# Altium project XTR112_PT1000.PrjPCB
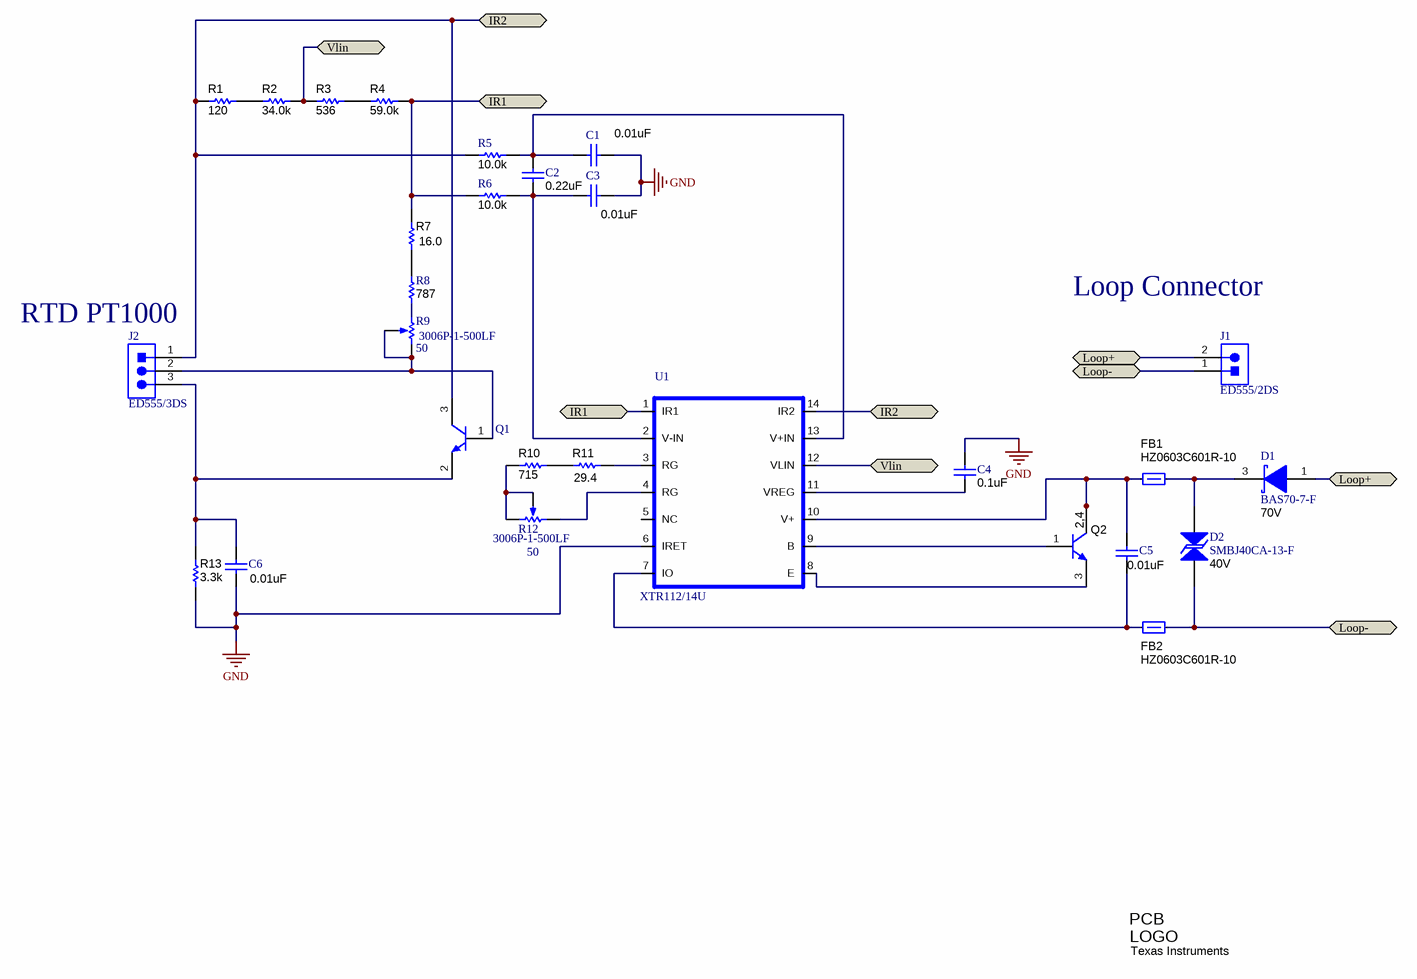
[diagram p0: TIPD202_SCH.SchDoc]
TechSupport: http://www.ti.com/support; SCH_Rev: A; PRJ_Title: Linearized 3-wire PT1000 RTD to 2-wire 4-20mA; PRJ_Customer: Public Release; PRJ_BasePN: TIPD202; PCB_SilkRev: REV A; PCB_CopperRev: 001; CopyrightYear: 2015
1 sheet, 29 parts. Net scope: flat (ports and power ports of the same name join across sheets).
Board file: XTR112_PT1000.PcbDoc

## Sheet TIPD202_SCH.SchDoc: TIPD202 Schematic
size 431 x 279 mm; Date: Not shown in title block; ApprovedBy: Not shown in title block; CheckedBy: Not shown in title block; Author: Not shown in title block; CompanyName: Not shown in title block; Engineer: Not shown in title block; Organization: Not shown in title block; Address1: Not shown in title block; Address2: Not shown in title block; Address3: Not shown in title block; Address4: Not shown in title block; DocumentNumber: 1; Revision: Use project parameter SCH_Rev; SheetNumber: 1; SheetTotal: 1; PageSetup: Record=PageOptions¦CenterHorizontal=True¦CenterVertical=True¦PrintScale=1.00¦XCorrection=1.00¦YCorrection=1.00¦PrintKind=0¦BorderSize=5000000¦LeftOffset=0¦BottomOffset=0¦Orientation=2¦PaperLength=1000¦PaperWidth=1000¦Scale=100¦PaperSource=15¦PrintQuality=600¦MediaType=1¦DitherType=10¦PaperKind=Letter¦PrintScaleMode=1

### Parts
C1  value 0.01uF  [0805_HV]  (hidden comment: C2012C0G1H103J)
C2  value 0.22uF  [0805_HV]  (hidden comment: GRM21BR71H224KA01L)
C3  value 0.01uF  [0805_HV]  (hidden comment: C2012C0G1H103J)
C4  value 0.1uF  [0805_HV]  (hidden comment: 08055C104KAT2A)
C5  value 0.01uF  [0805_HV]  (hidden comment: GRM216R71H103KA01D)
C6  value 0.01uF  [0805_HV]  (hidden comment: GRM216R71H103KA01D)
D1  BAS70-7-F  value 70V  [SOT-23]
D2  SMBJ40CA-13-F  value 40V  [SMB]
FB1  value HZ0603C601R-10  [0603]  (hidden comment: Used in BOM report)
FB2  value HZ0603C601R-10  [0603]  (hidden comment: Used in BOM report)
J1  ED555/2DS  [TERM_BLK_ED555-2DS]
J2  ED555/3DS  [TERM_BLK_ED555-3DS]
Logo1  Texas Instruments  [TI_Stacked_Overlay_Small]  (no BOM)
Q1  BC847CLT1G  [SOT-23]  (value not drawn)
Q2  FCX690BTA  [SOT-89-3]  (value not drawn)
R1  ValueDisplayed: 120  [0805_HV]  (hidden comment: RG2012P-121-B-T5)
R2  ValueDisplayed: 34.0k  [0805_HV]  (hidden comment: RT0805BRD0734KL)
R3  ValueDisplayed: 536  [0805_HV]  (hidden comment: RT0805BRD07536RL)
R4  ValueDisplayed: 59.0k  [0805_HV]  (hidden comment: RT0805BRD0759KL)
R5  value 10.0k  [0805_HV]  (hidden comment: CRCW080510K0FKEA)
R6  value 10.0k  [0805_HV]  (hidden comment: CRCW080510K0FKEA)
R7  value 16.0  [0805_HV]  (hidden comment: RT0805BRD0716RL)
R8  value 787  [0805_HV]  (hidden comment: RT0805BRD07787RL)
R9  3006P-1-500LF  value 50  [BOURNS_3006P]
R10  ValueDisplayed: 715  [0805_HV]  (hidden comment: RT0805BRD07715RL)
R11  value 29.4  [0805_HV]  (hidden comment: RT0805BRD0729R4L)
R12  3006P-1-500LF  value 50  [BOURNS_3006P]
R13  ValueDisplayed: 3.3k  [0805_HV]  (hidden comment: CRCW08053K30JNEA)
U1  XTR112/14U  [SO14]

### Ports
IR1, IR2, Loop+, Loop-, Vlin

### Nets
GND: C1.1 C3.1 C4.1 C6.2 R13.1 U1.6(IRET)
NetC1_2: C1.2 C2.1 R5.2 U1.13(V+IN)
NetC2_2: C2.2 C3.2 R6.2 U1.2(V-IN)
NetC4_2: C4.2 U1.11(VREG)
NetC5_1: C5.1 FB1.1 Q2.2(C) Q2.4(C) U1.10(V+)
NetC5_2: C5.2 FB2.1 U1.7(IO)
NetC6_1: C6.1 J2.3 Q1.2(E) R13.2
NetD1_1: D1.1(A) J1.2 ; port Loop+
NetD1_3: D1.3(K) D2.2 FB1.2
NetD2_1: D2.1 FB2.2 J1.1 ; port Loop-
NetJ2_1: J2.1 Q1.3(C) R1.1 R5.1 U1.14(IR2) ; port IR2
NetJ2_2: J2.2 Q1.1(B) R9.2(WIPER) R9.3(CW)
NetQ2_1: Q2.1(B) U1.9(B)
NetQ2_3: Q2.3(E) U1.8(E)
NetR1_2: R1.2 R2.1
NetR2_2: R2.2 R3.1 U1.12(VLIN) ; port Vlin
NetR3_2: R3.2 R4.1
NetR4_2: R4.2 R6.1 R7.2 U1.1(IR1) ; port IR1
NetR7_1: R7.1 R8.2
NetR8_1: R8.1 R9.1(CCW)
NetR10_1: R10.1 R12.2(WIPER) R12.3(CW)
NetR10_2: R10.2 R11.1
NetR11_2: R11.2 U1.3(RG)
NetR12_1: R12.1(CCW) U1.4(RG)

Not connected (* = marked no-connect by the designer): U1 5(NC)

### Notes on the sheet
- (near J2) RTD PT1000
- Loop Connector

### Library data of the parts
C1 C3 = C2012C0G1H103J: CAP, CERM, 0.01uF, 50V, +/-5%, C0G/NP0, 0805; Manufacturer: TDK; Polarized: N; CompType: Capacitor; ValueDisplayed: 0.01µF; U/M: EA; Cap_F: 0.00000001; Tolerance_%: 5; Value1: Unknown; VDC_V: 50; TaMin_C: -55; TaMax_C: 125; Cap_Case: 0805
C2 = GRM21BR71H224KA01L: CAP, CERM, 0.22uF, 50V, +/-10%, X7R, 0805; Manufacturer: MuRata; Polarized: N; CompType: Capacitor; ValueDisplayed: 0.22µF; U/M: EA; Cap_F: 0.00000022; Tolerance_%: 10; Value1: Unknown; VDC_V: 50; TaMin_C: -55; TaMax_C: 125; Cap_Case: 0805
C4 = 08055C104KAT2A: CAP, CERM, 0.1uF, 50V, +/-10%, X7R, 0805; Manufacturer: AVX; Polarized: N; CompType: Capacitor; ValueDisplayed: 0.1µF; U/M: EA; Cap_F: 0.0000001; Tolerance_%: 10; ESR_Ohm: 0.024; Value1: 0.024 ohm; VDC_V: 50; TaMin_C: -55; TaMax_C: 125; Cap_Case: 0805
C5 C6 = GRM216R71H103KA01D: CAP, CERM, 0.01uF, 50V, +/-10%, X7R, 0805; Manufacturer: MuRata; Polarized: N; CompType: Capacitor; ValueDisplayed: 0.01µF; U/M: EA; Cap_F: 0.00000001; Tolerance_%: 10; Value1: Unknown; VDC_V: 50; TaMin_C: -55; TaMax_C: 125; Cap_Case: 0805
D1 = BAS70-7-F: Diode, Schottky, 70V, 0.07A, SOT-23; Manufacturer: Diodes Inc.; U/M: EA; Vf_V: 0.41; Value2: 0.41V; Io_A: 0.07; Vr_V: 70; TJmax_C: 125
D2 = SMBJ40CA-13-F: Diode, TVS, Bi, 40V, 600W, SMB; Manufacturer: Diodes Inc.; U/M: EA; Power_W: 600; Vr_V: 40
FB1 FB2 = Ferrite_Bead: 300mA Ferrite Bead, 600 ohm @ 100MHz; U/M: EA
J1 = ED555/2DS: Terminal Block, 6A, 3.5mm Pitch, 2-Pos, TH; Manufacturer: On-Shore Technology; SymbolCreator: a0412235; CompType: Connector; U/M: EA
J2 = ED555/3DS: Terminal Block, 6A, 3.5mm Pitch, 3-Pos, TH; Manufacturer: On-Shore Technology; SymbolCreator: a0799628; CompType: Connector; U/M: EA
Logo1 = TI_Logo: Texas Instrument Corporate Signature; SymbolCreator: a0412235
Q1 = BC847CLT1G, ON Semiconductor: Transistor, NPN, 45V, 0.1A, SOT-23; CompType: BJT; PNP: 0; NPN: 1; Vceo_V: 45; Vcesat1_V: 0.7; Value: 0.7V; IcRated_A: 0.1; HfeMax: 800; TaMin_C: -55; TaMax_C: 150; U/M: EA
Q2 = FCX690BTA, Diodes Inc.: Transistor, NPN, 45V, 1A, SOT-89; Alternate Manufacturer: None; CompType: BJT; U/M: EA; PNP: 0; NPN: 1; Vceo_V: 45; Vcesat1_V: 0.08; Value: 0.08V
R1 = RG2012P-121-B-T5: RES, 120, 0.1%, 0.125 W, 0805; Manufacturer: Susumu Co Ltd; CompType: Resistor; Value: 120; Value_Code: 120R; Tolerance_%: 0.1; Power_W: 0.125; Value2: 0.125W; VDC_V: 100; TempCo: 25 ppm/C; EIA_Code: E192; U/M: EA
R2 = RT0805BRD0734KL: RES, 34.0 k, 0.1%, 0.125 W, 0805; Manufacturer: Yageo America; CompType: Resistor; Value: 34.0k; Res_ohm: 34000; Value_Code: 34k0; Tolerance_%: 0.1; Power_W: 0.125; Value2: 0.125W; VDC_V: 150; TempCo: 25 ppm/C; EIA_Code: E192; U/M: EA
R3 = RT0805BRD07536RL: RES, 536, 0.1%, 0.125 W, 0805; Manufacturer: Yageo America; CompType: Resistor; Value: 536; Value_Code: 536R; Tolerance_%: 0.1; Power_W: 0.125; Value2: 0.125W; VDC_V: 150; TempCo: 25 ppm/C; EIA_Code: E192; U/M: EA
R4 = RT0805BRD0759KL: RES, 59.0 k, 0.1%, 0.125 W, 0805; Manufacturer: Yageo America; CompType: Resistor; Value: 59.0k; Res_ohm: 59000; Value_Code: 59k0; Tolerance_%: 0.1; Power_W: 0.125; Value2: 0.125W; VDC_V: 150; TempCo: 25 ppm/C; EIA_Code: E192; U/M: EA
R5 R6 = CRCW080510K0FKEA: RES, 10.0k ohm, 1%, 0.125W, 0805; Manufacturer: Vishay-Dale; CompType: Resistor; Res_ohm: 10000; Value_Code: 10k0; Tolerance_%: 1; Power_W: 0.125; VDC_V: 150; TempCo: 100 ppm/C; EIA_Code: E96; U/M: EA
R7 = RT0805BRD0716RL: RES, 16.0, 0.1%, 0.125 W, 0805; Manufacturer: Yageo America; CompType: Resistor; Res_ohm: 16; Value_Code: 16R0; Tolerance_%: 0.1; Power_W: 0.125; Value2: 0.125W; VDC_V: 150; TempCo: 25 ppm/C; EIA_Code: E192; U/M: EA; AEC Category: Q200
R8 = RT0805BRD07787RL: RES, 787 ohm, 0.1%, 0.125W, 0805; Manufacturer: Yageo America; CompType: Resistor; Value_Code: 787R; Tolerance_%: 0.1; Power_W: 0.125; VDC_V: 150; TempCo: 25 ppm/C; EIA_Code: E192; U/M: EA
R9 R12 = 3006P-1-500LF: TRIMMER, 10K, 0.75W, TH; Manufacturer: Bourns; Sim Note: Enter the Resistance value and the set point into parameter fields.; SymbolCreator: a0222586
R10 = RT0805BRD07715RL: RES, 715, 0.1%, 0.125 W, 0805; Manufacturer: Yageo America; CompType: Resistor; Value: 715; Value_Code: 715R; Tolerance_%: 0.1; Power_W: 0.125; Value2: 0.125W; VDC_V: 150; TempCo: 25 ppm/C; EIA_Code: E192; U/M: EA
R11 = RT0805BRD0729R4L: RES, 29.4, 0.1%, 0.125 W, 0805; Manufacturer: Yageo America; CompType: Resistor; Value_Code: 29R4; Tolerance_%: 0.1; Power_W: 0.125; Value2: 0.125W; VDC_V: 150; TempCo: 25 ppm/C; EIA_Code: E192; U/M: EA
R13 = CRCW08053K30JNEA: RES, 3.3 k, 5%, 0.125 W, 0805; Manufacturer: Vishay-Dale; CompType: Resistor; Value: 3.3k; Res_ohm: 3300; Value_Code: 3k30; Tolerance_%: 5; Power_W: 0.125; Value2: 0.125W; VDC_V: 150; TempCo: 200 ppm/C; EIA_Code: E24; U/M: EA; AEC Category: Q200
U1 = XTR112/14U: IC, 4-20mA Current Transmitter with Sensor Excitation and Linearization; Manufacturer: TI; PartNumber: XTR11xU; Alternate Manufacturer: None; Area: 132000; Value: XTR11xU

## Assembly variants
-100A: all parts fitted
